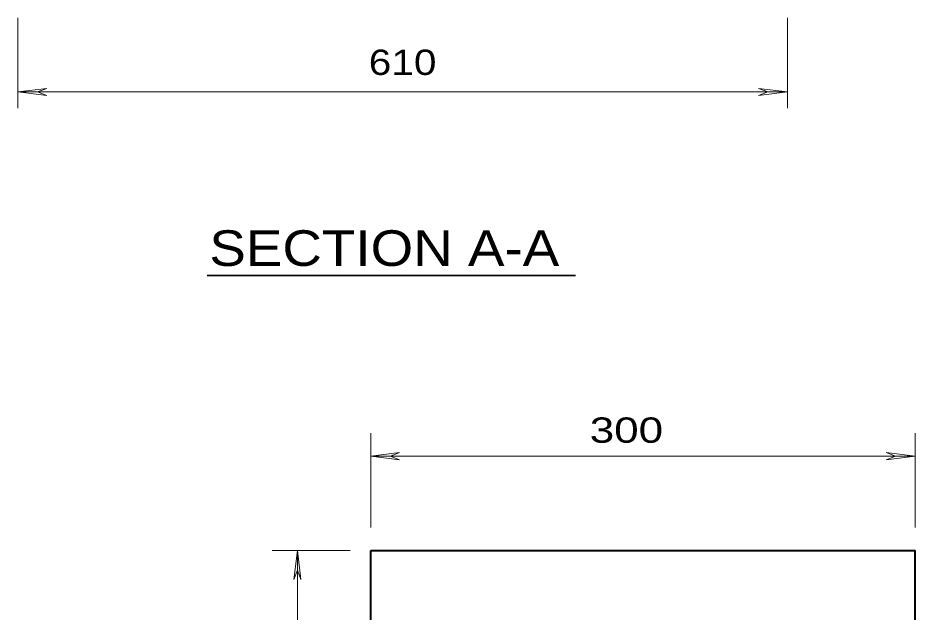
# Model space of a CAD drawing. Extents: x 312583 to 312854, y 144419 to 144597.
# Drawn here: x 312690.6 to 312717.56, y 144489.1 to 144506.95 of the extents above; entities that cross this region are included whole.
import ezdxf
from ezdxf.enums import TextEntityAlignment as Align

# ---------------------------------------------------------------- set-up
doc = ezdxf.new("R2010")
doc.units = 0
doc.header["$LTSCALE"] = 0.3
doc.layers.add('1', color=7, linetype='Continuous', lineweight=25)
doc.layers.add('2', color=7, linetype='Continuous', lineweight=13)

msp = doc.modelspace()

# ---------------------------------------------------------------- linework, layer by layer
at = {"layer": '1', "lineweight": 40}
for p, q in [((312701.2082, 144474.5943), (312701.2082, 144490.9473)), ((312701.2082, 144490.9473), (312717.5612, 144490.9473))]:
    msp.add_line(p, q, dxfattribs=at)
msp.add_lwpolyline([(312701.2082, 144474.5943), (312717.5612, 144474.5943), (312717.5612, 144490.9473)], dxfattribs=at)
at = {"layer": '2'}
for p, q in [((312690.6048, 144506.946), (312690.6048, 144504.232)), ((312713.7275, 144506.946), (312713.7275, 144504.232)), ((312690.6048, 144504.7227), (312691.4711, 144504.83)), ((312690.6048, 144504.7227), (312713.7275, 144504.7227)), ((312690.6048, 144504.7227), (312691.4711, 144504.6154)), ((312691.4711, 144504.83), (312691.1951, 144504.7227)), ((312691.4711, 144504.6154), (312691.1951, 144504.7227)), ((312712.8611, 144504.83), (312713.1371, 144504.7227)), ((312713.7275, 144504.7227), (312712.8611, 144504.83)), ((312712.8611, 144504.6154), (312713.1371, 144504.7227)), ((312713.7275, 144504.7227), (312712.8611, 144504.6154)), ((312701.2082, 144491.6373), (312701.2082, 144494.474)), ((312717.5612, 144491.6373), (312717.5612, 144494.474)), ((312701.2082, 144493.784), (312702.0746, 144493.8913)), ((312702.0746, 144493.8913), (312701.7986, 144493.784)), ((312716.6949, 144493.8913), (312716.9709, 144493.784)), ((312717.5612, 144493.784), (312716.6949, 144493.8913)), ((312701.2082, 144493.784), (312702.0746, 144493.6767)), ((312701.2082, 144493.784), (312717.5612, 144493.784)), ((312702.0746, 144493.6767), (312701.7986, 144493.784)), ((312716.6949, 144493.6767), (312716.9709, 144493.784)), ((312717.5612, 144493.784), (312716.6949, 144493.6767)), ((312700.5872, 144490.9473), (312698.2412, 144490.9473)), ((312699.0002, 144490.9473), (312698.8929, 144490.081)), ((312699.0002, 144490.9473), (312699.1076, 144490.081)), ((312699.0002, 144474.5943), (312699.0002, 144490.9473)), ((312698.8929, 144490.081), (312699.0002, 144490.357)), ((312699.1076, 144490.081), (312699.0002, 144490.357))]:
    msp.add_line(p, q, dxfattribs=at)
at = {"layer": '2', "lineweight": 35}
msp.add_line((312696.2887, 144499.2104), (312707.3571, 144499.2104), dxfattribs=at)

# ---------------------------------------------------------------- texts
at = {"layer": '2'}
for s, width, p in [('610 ', 1.2, (312701.1457, 144505.2339)), ('300 ', 1.3, (312707.7859, 144494.1856))]:
    msp.add_text(s, height=0.76, dxfattribs=dict(at, width=width)).set_placement(p)
at = {"layer": '2', "width": 1.15}
msp.add_text('SECTION A-A', height=1.07, dxfattribs=at).set_placement((312701.6125, 144499.4972), align=Align.CENTER)

doc.saveas('drawing.dxf')
